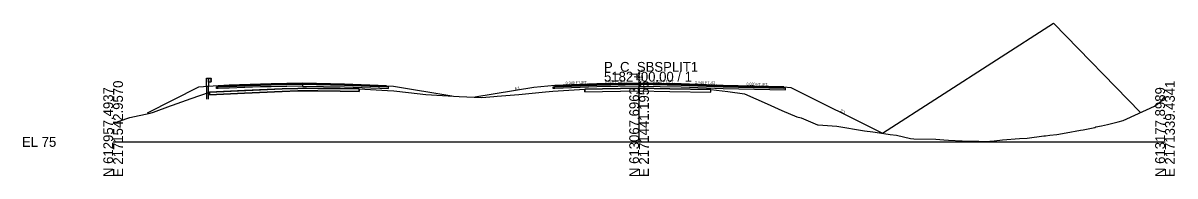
# Model space of a CAD drawing. Extents: x -26 to 1303, y -3010 to 12033.
# Drawn here: x -25.7 to 302.8, y 5490.3 to 5533.9 of the extents above; entities that cross this region are included whole.
import ezdxf

# ---------------------------------------------------------------- set-up
doc = ezdxf.new("R2010")
doc.units = 0
for name, color, linetype in [('RD_GPK_XS_Cell', 7, 'Continuous'), ('RD_PD_Final_TrvlWay', 7, 'Continuous'), ('RD_Sketch10', 7, 'Continuous'), ('RD_XS_Base', 7, 'Continuous'), ('RD_XS_ExGround', 7, 'Continuous'), ('RD_XS_ExPaveRet', 7, 'Continuous'), ('RD_XS_GR', 7, 'Continuous'), ('RD_XS_Greenside', 7, 'Continuous'), ('RD_XS_Pave', 7, 'Continuous'), ('RD_XS_PaveOvlay_CP', 7, 'Continuous'), ('RD_XS_TieSlope', 7, 'Continuous'), ('RD_XS_TX_Elev_EX', 7, 'Continuous'), ('RD_XS_TX_Elev_PR', 7, 'Continuous'), ('RD_XS_TX_Slope', 7, 'Continuous')]:
    doc.layers.add(name, color=color, linetype=linetype)

msp = doc.modelspace()

# ---------------------------------------------------------------- linework, layer by layer
at = {"layer": 'RD_GPK_XS_Cell'}
for p, q in [((150, 5500), (150, 5520)), ((0, 5500), (150, 5500)), ((150, 5500), (300, 5500))]:
    msp.add_line(p, q, dxfattribs=at)
at = {"layer": 'RD_PD_Final_TrvlWay'}
msp.add_lwpolyline([(27.17, 5512.19), (27.17, 5515.8), (26.67, 5515.76), (26.67, 5512.19)], dxfattribs=at)
at = {"layer": 'RD_Sketch10'}
msp.add_lwpolyline([(219.45, 5502.46), (268.23, 5533.89), (293.03, 5508.37)], dxfattribs=at)
at = {"layer": 'RD_XS_Base'}
for p, q in [((33.12, 5515.83), (42, 5516.19)), ((42, 5516.19), (45.12, 5516.25)), ((45.12, 5516.25), (54, 5516.43)), ((54, 5516.47), (54, 5516.58)), ((54, 5516.58), (54, 5516.1)), ((54, 5516.43), (54, 5516.58)), ((54, 5516.58), (54, 5515.93)), ((54, 5516.43), (54, 5516.47)), ((54, 5516.43), (54, 5516.06)), ((54, 5516.43), (54, 5515.93)), ((66, 5516.19), (54, 5516.43)), ((54, 5516.43), (54, 5516.43)), ((54, 5516.1), (54, 5515.93)), ((78, 5515.71), (66, 5516.19)), ((68, 5516.11), (68, 5516.11)), ((126, 5515.72), (138, 5516.2)), ((138, 5516.2), (150, 5516.44)), ((150, 5516.44), (150, 5516.6)), ((150, 5516.6), (150, 5515.94)), ((150, 5516.44), (150, 5516.44)), ((162, 5516.2), (150, 5516.44)), ((150, 5516.44), (150, 5516.44)), ((150, 5516.44), (150, 5515.94)), ((174, 5515.72), (162, 5516.2)), ((162, 5516.2), (162, 5516.2)), ((29.5, 5515.32), (29.5, 5515.69)), ((29.5, 5515.69), (29.63, 5515.69)), ((29.5, 5515.19), (29.5, 5515.32)), ((29.63, 5515.19), (29.5, 5515.19)), ((29.63, 5515.69), (30, 5515.71)), ((30, 5515.21), (29.63, 5515.19)), ((30, 5515.71), (33.12, 5515.83)), ((33.12, 5515.33), (30, 5515.21)), ((42, 5515.69), (33.12, 5515.33)), ((45.12, 5515.75), (42, 5515.69)), ((54, 5515.93), (45.12, 5515.75)), ((54, 5516.06), (54, 5515.93)), ((54, 5515.93), (54, 5515.93)), ((54, 5515.93), (54, 5515.93)), ((54, 5515.93), (66, 5515.69)), ((66, 5515.69), (78.5, 5515.19)), ((68, 5515.61), (68, 5515.61)), ((78.5, 5515.69), (78, 5515.71)), ((78, 5515.71), (78, 5515.71)), ((78.5, 5515.19), (78.5, 5515.69)), ((78.5, 5515.69), (78.5, 5515.69)), ((78.5, 5515.19), (78.5, 5515.19)), ((78.5, 5515.19), (78.5, 5515.19)), ((125.5, 5515.7), (126, 5515.72)), ((125.5, 5515.2), (125.5, 5515.7)), ((125.5, 5515.7), (125.5, 5515.7)), ((126, 5515.22), (125.5, 5515.2)), ((125.5, 5515.2), (125.5, 5515.2)), ((125.5, 5515.2), (125.5, 5515.2)), ((126, 5515.72), (126, 5515.72)), ((138, 5515.7), (126, 5515.22)), ((126, 5515.22), (126, 5515.22)), ((150, 5515.94), (138, 5515.7)), ((150, 5515.94), (150, 5515.94)), ((150, 5515.94), (162, 5515.7)), ((150, 5515.94), (150, 5515.94)), ((162, 5515.7), (162, 5515.7)), ((162, 5515.7), (174, 5515.22)), ((191.3, 5515.37), (174, 5515.72)), ((174, 5515.72), (174, 5515.72)), ((174, 5515.22), (174, 5515.22)), ((174, 5515.22), (191.8, 5514.86)), ((191.8, 5515.36), (191.3, 5515.37)), ((191.3, 5515.37), (191.3, 5515.37)), ((191.8, 5514.86), (191.8, 5515.36)), ((191.8, 5515.36), (191.8, 5515.36)), ((191.8, 5514.86), (191.8, 5514.86)), ((191.8, 5514.86), (191.8, 5514.86))]:
    msp.add_line(p, q, dxfattribs=at)
at = {"layer": 'RD_XS_ExGround'}
msp.add_lwpolyline([(0, 5505.59), (0.99, 5505.68), (1.69, 5505.93), (4.77, 5506.99), (10.52, 5508.24), (11.49, 5508.5), (16.32, 5510.27), (16.9, 5510.5), (22.22, 5512.36), (27.5, 5514.19), (48.22, 5515.1), (54.09, 5515.32), (58.38, 5515.27), (70.21, 5515.13), (78.28, 5514.62), (80.05, 5514.52), (84.2, 5514.08), (89.21, 5513.49), (98.73, 5512.99), (105.14, 5512.65), (108.62, 5512.96), (109.55, 5513), (115.74, 5513.5), (123.3, 5514.28), (125.44, 5514.5), (134.57, 5515.04), (134.58, 5515.04), (134.58, 5515.04), (134.58, 5515.04), (134.58, 5515.04), (149.77, 5515.32), (158.81, 5515.14), (170.43, 5514.9), (175.34, 5514.36), (180.04, 5513.75), (186.54, 5510.82), (190.72, 5508.97), (195.04, 5507.14), (196.22, 5506.84), (200.85, 5504.91), (201.05, 5504.9), (203.74, 5504.65), (206.4, 5504.52), (214.28, 5503.21), (216.65, 5502.9), (218.61, 5502.6), (221.62, 5502.09), (223.43, 5501.95), (227.37, 5500.98), (228.41, 5500.86), (234.64, 5500.82), (236.89, 5500.57), (238.28, 5500.5), (242.11, 5500.31), (243.66, 5500.2), (246.88, 5500.23), (248.75, 5500.11), (251.29, 5500.35), (253.66, 5500.56), (258.49, 5500.95), (260.69, 5501.04), (265.43, 5501.76), (265.81, 5501.77), (265.92, 5501.77), (267.18, 5501.94), (269.16, 5502.09), (271.82, 5502.55), (275.93, 5503.31), (276.68, 5503.45), (279.94, 5504.15), (280.24, 5504.28), (281.9, 5504.58), (283.6, 5505.01), (286.65, 5505.69), (288.09, 5506.13), (289.09, 5506.58), (296.98, 5510.17), (298.89, 5511.66), (300, 5513.03)], dxfattribs=at)
at = {"layer": 'RD_XS_ExPaveRet'}
for p, q in [((134.58, 5515.04), (134.58, 5514.29)), ((170.43, 5514.15), (170.43, 5514.9))]:
    msp.add_line(p, q, dxfattribs=at)
for points in [[(64.75, 5515.2), (70.21, 5515.13), (70.21, 5514.79), (70.21, 5514.38), (64.75, 5514.45), (58.38, 5514.52), (55.12, 5514.56), (54.09, 5514.57), (52.69, 5514.52), (48.22, 5514.35), (37.43, 5513.88), (27.5, 5513.44), (27.5, 5513.44), (27.5, 5513.79), (27.5, 5514.19), (27.5, 5514.19), (37.43, 5514.63), (48.22, 5515.1), (52.69, 5515.27), (54.09, 5515.32), (55.12, 5515.31), (58.38, 5515.27), (64.75, 5515.2)], [(58.38, 5515.27), (55.12, 5515.31), (54.09, 5515.32), (52.69, 5515.27), (48.22, 5515.1), (37.43, 5514.63), (27.5, 5514.19), (27.5, 5513.79), (27.5, 5513.44), (37.43, 5513.88), (48.22, 5514.35), (52.69, 5514.52), (54.09, 5514.57), (55.12, 5514.56), (58.38, 5514.52), (64.75, 5514.45), (70.21, 5514.38), (70.21, 5514.79), (70.21, 5515.13), (64.75, 5515.2), (58.38, 5515.27)], [(170.43, 5514.9), (158.81, 5515.14), (149.78, 5515.32), (149.77, 5515.32), (149.76, 5515.32), (134.58, 5515.04)], [(170.43, 5514.9), (158.81, 5515.14), (149.78, 5515.32), (149.77, 5515.32), (149.76, 5515.32), (134.58, 5515.04)], [(134.58, 5514.29), (134.58, 5515.04)], [(134.58, 5514.29), (149.76, 5514.57), (149.77, 5514.57), (149.78, 5514.57), (158.81, 5514.39), (170.43, 5514.15)], [(134.58, 5514.29), (149.76, 5514.57), (149.77, 5514.57), (149.78, 5514.57), (158.81, 5514.39), (170.43, 5514.15)], [(170.43, 5514.15), (170.43, 5514.9)]]:
    msp.add_lwpolyline(points, dxfattribs=at)
at = {"layer": 'RD_XS_GR'}
for p, q in [((26.67, 5515.76), (26.67, 5518.19)), ((26.67, 5518.19), (26.92, 5518.19)), ((26.92, 5518.19), (27.17, 5518.19)), ((27.17, 5518.19), (27.17, 5515.8)), ((27.17, 5517.03), (27.17, 5518.19)), ((27.17, 5518.19), (27.83, 5518.19)), ((27.83, 5517.03), (27.17, 5517.03)), ((27.83, 5518.19), (27.83, 5517.03)), ((28.03, 5517.98), (27.83, 5518.19)), ((27.83, 5518.19), (27.83, 5517.33)), ((27.83, 5517.61), (27.9, 5517.68)), ((28.03, 5517.39), (27.83, 5517.61)), ((27.83, 5517.33), (27.83, 5517.03)), ((27.83, 5517.03), (27.9, 5517.1)), ((27.9, 5517.68), (28.1, 5517.9)), ((27.9, 5517.1), (28.1, 5517.32)), ((28.1, 5517.9), (28.03, 5517.98)), ((28.1, 5517.32), (28.03, 5517.39)), ((27.17, 5515.8), (26.67, 5515.76))]:
    msp.add_line(p, q, dxfattribs=at)
at = {"layer": 'RD_XS_Greenside'}
for p, q in [((24.35, 5515.57), (9.7, 5508.24)), ((80, 5515.86), (96.61, 5513.1)), ((120, 5515.56), (103.18, 5512.75)), ((193.3, 5515.53), (219.45, 5502.46))]:
    msp.add_line(p, q, dxfattribs=at)
at = {"layer": 'RD_XS_Pave'}
for p, q in [((33.12, 5516.15), (30, 5516.02)), ((42, 5516.5), (33.12, 5516.15)), ((42, 5516.34), (33.12, 5515.99)), ((33.12, 5515.99), (42, 5516.34)), ((33.12, 5515.83), (42, 5516.19)), ((45.12, 5516.57), (42, 5516.5)), ((45.12, 5516.41), (42, 5516.34)), ((42, 5516.34), (45.12, 5516.41)), ((42, 5516.19), (45.12, 5516.25)), ((54, 5516.74), (45.12, 5516.57)), ((54, 5516.58), (45.12, 5516.41)), ((45.12, 5516.41), (54, 5516.58)), ((45.12, 5516.25), (54, 5516.43)), ((66, 5516.5), (54, 5516.74)), ((54, 5516.47), (54, 5516.58)), ((54, 5516.58), (54, 5516.47)), ((54, 5516.43), (54, 5516.58)), ((54, 5516.58), (66, 5516.34)), ((66, 5516.34), (54, 5516.58)), ((54, 5516.58), (54, 5516.43)), ((54, 5516.43), (54, 5516.47)), ((54, 5516.47), (54, 5516.43)), ((54, 5516.43), (54, 5516.43)), ((54, 5516.43), (54, 5516.43)), ((54, 5516.43), (66, 5516.19)), ((78, 5516.02), (66, 5516.5)), ((66, 5516.34), (78, 5515.86)), ((78, 5515.86), (66, 5516.34)), ((66, 5516.19), (78, 5515.71)), ((68, 5516.42), (68, 5516.42)), ((68, 5516.26), (68, 5516.26)), ((68, 5516.26), (68, 5516.26)), ((68, 5516.11), (68, 5516.11)), ((138, 5516.52), (126, 5516.04)), ((138, 5516.36), (126, 5515.88)), ((126, 5515.88), (138, 5516.36)), ((126, 5515.72), (138, 5516.2)), ((150, 5516.76), (138, 5516.52)), ((150, 5516.6), (138, 5516.36)), ((138, 5516.36), (150, 5516.6)), ((138, 5516.2), (150, 5516.44)), ((162, 5516.52), (150, 5516.76)), ((150, 5516.44), (150, 5516.6)), ((150, 5516.6), (162, 5516.36)), ((162, 5516.36), (150, 5516.6)), ((150, 5516.6), (150, 5516.6)), ((150, 5516.6), (150, 5516.44)), ((150, 5516.44), (150, 5516.44)), ((150, 5516.44), (150, 5516.44)), ((150, 5516.44), (150, 5516.44)), ((150, 5516.44), (162, 5516.2)), ((174, 5516.04), (162, 5516.52)), ((162, 5516.52), (162, 5516.52)), ((162, 5516.36), (162, 5516.36)), ((162, 5516.36), (174, 5515.88)), ((174, 5515.88), (162, 5516.36)), ((162, 5516.36), (162, 5516.36)), ((162, 5516.2), (162, 5516.2)), ((162, 5516.2), (174, 5515.72)), ((30, 5516.02), (30, 5515.91)), ((33.12, 5515.99), (30, 5515.86)), ((30, 5515.86), (33.12, 5515.99)), ((30, 5515.91), (30, 5515.86)), ((30, 5515.86), (30, 5515.75)), ((30, 5515.71), (33.12, 5515.83)), ((30, 5515.75), (30, 5515.71)), ((78, 5515.86), (78, 5516.02)), ((78, 5516.02), (78, 5516.02)), ((78, 5515.86), (78, 5515.86)), ((78, 5515.86), (78, 5515.86)), ((78, 5515.71), (78, 5515.86)), ((78, 5515.86), (78, 5515.86)), ((78, 5515.71), (78, 5515.71)), ((78, 5515.71), (78, 5515.71)), ((126, 5516.04), (126, 5516.04)), ((126, 5516.04), (126, 5515.88)), ((126, 5515.88), (126, 5515.88)), ((126, 5515.88), (126, 5515.72)), ((126, 5515.88), (126, 5515.88)), ((126, 5515.88), (126, 5515.88)), ((126, 5515.72), (126, 5515.72)), ((126, 5515.72), (126, 5515.72)), ((191.3, 5515.69), (174, 5516.04)), ((174, 5516.04), (174, 5516.04)), ((174, 5515.88), (174, 5515.88)), ((174, 5515.88), (191.3, 5515.53)), ((191.3, 5515.53), (174, 5515.88)), ((174, 5515.88), (174, 5515.88)), ((174, 5515.72), (174, 5515.72)), ((174, 5515.72), (191.3, 5515.37)), ((191.3, 5515.53), (191.3, 5515.69)), ((191.3, 5515.69), (191.3, 5515.69)), ((191.3, 5515.53), (191.3, 5515.53)), ((191.3, 5515.53), (191.3, 5515.53)), ((191.3, 5515.37), (191.3, 5515.53)), ((191.3, 5515.53), (191.3, 5515.53)), ((191.3, 5515.37), (191.3, 5515.37)), ((191.3, 5515.37), (191.3, 5515.37))]:
    msp.add_line(p, q, dxfattribs=at)
at = {"layer": 'RD_XS_PaveOvlay_CP'}
for p, q in [((30, 5516.02), (42, 5516.5)), ((42, 5516.5), (54, 5516.74)), ((54, 5516.74), (66, 5516.5)), ((66, 5516.5), (78, 5516.02)), ((138, 5516.52), (126, 5516.04)), ((150, 5516.76), (138, 5516.52)), ((162, 5516.52), (150, 5516.76)), ((174, 5516.04), (162, 5516.52)), ((162, 5516.52), (162, 5516.52)), ((126, 5516.04), (126, 5516.04)), ((191.3, 5515.69), (174, 5516.04)), ((174, 5516.04), (174, 5516.04)), ((191.3, 5515.69), (191.3, 5515.69))]:
    msp.add_line(p, q, dxfattribs=at)
at = {"layer": 'RD_XS_TieSlope'}
for p, q in [((30, 5516.02), (24.35, 5515.57)), ((78, 5516.02), (80, 5515.86)), ((126, 5516.04), (120, 5515.56)), ((191.3, 5515.69), (193.3, 5515.53))]:
    msp.add_line(p, q, dxfattribs=at)

# ---------------------------------------------------------------- texts
at = {"layer": 'RD_GPK_XS_Cell'}
for s, p in [('P_C_SBSPLIT1', (140, 5520)), ('5182+00.00 / 1', (140, 5517.2)), ('EL 75', (-26, 5498.6))]:
    msp.add_text(s, height=2.8, dxfattribs=at).set_placement(p)
for s, p in [('E 2171542.9570', (2.8, 5490)), ('E 2171441.1956', (152.8, 5490)), ('E 2171339.4341', (302.8, 5490)), ('N 612957.4937', (0, 5490)), ('N 613067.6963', (150, 5490)), ('N 613177.8989', (300, 5490))]:
    msp.add_text(s, height=2.8, rotation=90, dxfattribs=at).set_placement(p)
at = {"layer": 'RD_XS_TX_Elev_EX'}
msp.add_text('90.31', height=0.6, rotation=90, dxfattribs=at).set_placement((149.76, 5517.6))
at = {"layer": 'RD_XS_TX_Elev_PR'}
msp.add_text('91.76', height=1, rotation=90, dxfattribs=at).set_placement((151.15, 5517.19))
at = {"layer": 'RD_XS_TX_Slope'}
for s, rotation, p in [('0.040 FT./FT.', 2.2906, (129.08, 5516.41)), ('0.020 FT./FT.', 1.1458, (140.22, 5516.84)), ('0.020 FT./FT.', 358.8542, (153.94, 5516.92)), ('0.040 FT./FT.', 357.7094, (165.94, 5516.61)), ('0.020 FT./FT.', 358.8542, (180.59, 5516.15)), ('6:1', 9.4623, (114.62, 5514.86)), ('2:1', 333.4349, (207.37, 5508.71))]:
    msp.add_text(s, height=0.75, rotation=rotation, dxfattribs=at).set_placement(p)

doc.saveas('drawing.dxf')
